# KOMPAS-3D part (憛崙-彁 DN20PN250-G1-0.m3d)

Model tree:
1. Объединить компоненты:1  (labels: СЕНС-ПР DN20PN250-G1-0)

Referenced files in D:\Савин\!СЕНСОР\3D для заказчика\!Новый перечень\СЕНС-ПР\5. СЕНС-ПР-PN250\DN20\: СЕНС-ПР DN20PN250-G1-0.a3d
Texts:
  СЕНС-ПР DN20PN250-G1-0
  ООО НПП Сенсор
